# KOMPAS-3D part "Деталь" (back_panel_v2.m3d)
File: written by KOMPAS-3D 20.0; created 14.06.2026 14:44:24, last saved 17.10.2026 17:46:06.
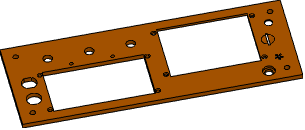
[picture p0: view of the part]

Document properties: Полное имя файла: D:\myProjects\Progect_esp32\box_compas\корпус\back_panel_v2.m3d

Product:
- Part/product: Деталь
    Материал: Фанера, береза,ФСФ ВВ/С ГОСТ 3916.1-2018 (density 760 kg/m3)
    Масса: 0.0227288

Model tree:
1. Эскиз:1
2. Элемент выдавливания:1
     Расстояние 1 = 4
3. Эскиз:4  (with: Элемент выдавливания:1)
4. Эскиз:5  (with: Элемент выдавливания:1)
5. Элемент выдавливания:5
     Расстояние 2 = 2
6. Эскиз:6  (with: Элемент выдавливания:1, Элемент выдавливания:5)
7. Элемент выдавливания:6
     Расстояние 2 = 4
8. Скругление:2  (with: Элемент выдавливания:5)
     Радиус = 1.5
9. Эскиз:16  (with: Элемент выдавливания:1)
10. Элемент выдавливания:19
     Расстояние 2 = 4
11. Эскиз:17  (with: Элемент выдавливания:1, Элемент выдавливания:19)
12. Элемент выдавливания:23
     Расстояние 2 = 4
13. Эскиз:20  (with: Элемент выдавливания:5, Элемент выдавливания:19)
14. Элемент выдавливания:24
     Расстояние 2 = 1.5
15. Скругление:7  (with: Элемент выдавливания:24)
     Радиус = 3
16. Эскиз:22  (with: Элемент выдавливания:5)
17. Элемент выдавливания:26
     Расстояние 1 = 2
18. Скругление:8  (with: Элемент выдавливания:26)
     Радиус = 0.5
19. Массив по сетке:5  (with: Элемент выдавливания:26, Эскиз:22, Скругление:8, Элемент выдавливания:5)  (10 pattern instances)
     Шаг 1 = 5; Угол раствора = 90
20. Эскиз:25  (with: Элемент выдавливания:5)
21. Элемент выдавливания:28
     Расстояние 1 = 2
22. Скругление:10  (with: Элемент выдавливания:28)
     Радиус = 0.5
23. Массив по сетке:7  (with: Элемент выдавливания:28, Эскиз:25, Скругление:10)  (17 pattern instances)
     Шаг 1 = 5; Угол раствора = 90
24. Эскиз:26  (with: Элемент выдавливания:5, Элемент выдавливания:28)
25. Элемент выдавливания:29
     Расстояние 1 = 2
26. Эскиз:27  (with: Элемент выдавливания:5, Элемент выдавливания:29, Элемент выдавливания:28)
27. Элемент выдавливания:30
     Расстояние 1 = 2
28. Массив по концентрической сетке:3  (with: Элемент выдавливания:23, Эскиз:17, Элемент выдавливания:19)  (5 pattern instances)
     Шаг 2 = 360
29. Эскиз:29  (with: Элемент выдавливания:5, Элемент выдавливания:1)
30. Элемент выдавливания:36
     Расстояние 2 = 2
31. Смещенная плоскость:1  (with: Элемент выдавливания:1)
     Расстояние = 13.75
32. Эскиз:32  (with: Элемент выдавливания:36)
33. Элемент вращения:3
     Угол 1 = 360
34. Элемент выдавливания:46
     Расстояние 2 = 4
35. Эскиз:2  (with: Элемент выдавливания:1, Элемент выдавливания:46)
36. Элемент выдавливания:2
     Расстояние 2 = 4
37. Массив по сетке:1  (with: Элемент выдавливания:2, Эскиз:2)  (4 pattern instances)
     Шаг 1 = 83; Угол раствора = 90; Шаг 2 = 37
38. Эскиз:39  (with: Элемент выдавливания:1, Элемент выдавливания:46)
39. Элемент выдавливания:48
     Расстояние 2 = 4
40. Массив по сетке:11  (with: Элемент выдавливания:48, Эскиз:39, Элемент выдавливания:1)  (4 pattern instances)
     Шаг 1 = 75.9; Угол раствора = 90; Шаг 2 = 44.2
41. Эскиз:40  (with: Элемент выдавливания:1, Элемент выдавливания:46)
42. Эскиз:35  (with: Элемент выдавливания:5, Элемент выдавливания:46, Скругление:2, Элемент выдавливания:2)
43. Элемент выдавливания:49
     Расстояние 2 = 2
44. Элемент выдавливания:50
     Расстояние 1 = 2
45. Скругление:14  (with: Элемент выдавливания:50)
     Радиус = 1
46. Эскиз:41  (with: Элемент выдавливания:5, Элемент выдавливания:48)
47. Элемент выдавливания:52
     Расстояние 1 = 0.5
48. Эскиз:42  (with: Элемент выдавливания:1, Элемент выдавливания:46)
49. Элемент выдавливания:55
     Расстояние 2 = 4
50. Эскиз:43  (with: Элемент выдавливания:29, Элемент выдавливания:1)
51. Элемент выдавливания:56
     Расстояние 2 = 0.5
52. Эскиз:44  (with: Элемент выдавливания:29, Элемент выдавливания:55)
53. Элемент выдавливания:57
     Расстояние 2 = 2
54. Эскиз:45  (with: Элемент выдавливания:5, Элемент выдавливания:26)
55. Элемент выдавливания:58
     Расстояние 1 = 2
56. Массив по сетке:12  (with: Элемент выдавливания:58, Эскиз:45)  (3 pattern instances)
     Шаг 1 = 10; Угол раствора = -90
57. Эскиз:46  (with: Элемент выдавливания:5, Элемент выдавливания:28)
58. Элемент выдавливания:59
     Расстояние 1 = 2
59. Массив по сетке:13  (with: Элемент выдавливания:59, Эскиз:46, Элемент выдавливания:1)  (7 pattern instances)
     Шаг 1 = 10; Угол раствора = 90
60. Эскиз:47  (with: Элемент выдавливания:5, Элемент выдавливания:36, Элемент выдавливания:58, Элемент выдавливания:26)
61. Элемент выдавливания:60
     Расстояние 2 = 0.75
62. Фаска:1  (with: Элемент выдавливания:48, Элемент выдавливания:2)
     Угол = 45; Длина 1 = 0.75; Длина 2 = 0.75
63. Эскиз:48  (with: Элемент выдавливания:1)  (labels: Фанера, береза,ФСФ ВВ/С ГОСТ 3916.1-2018)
